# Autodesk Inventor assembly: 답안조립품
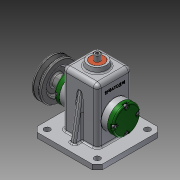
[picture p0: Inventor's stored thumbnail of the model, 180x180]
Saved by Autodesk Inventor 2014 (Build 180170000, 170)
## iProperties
Created: 2016-02
Part Number: 답안조립품
Document SubType Name: Assembly
Designer: Administrator
Author: Administrator
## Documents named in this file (16)
- C:\Users\Administrator\Desktop\460211V1036\답안조립품.iam
- C:\Users\Administrator\Desktop\460211V1036\1-본체.ipt
- C:\Users\Administrator\Desktop\460211V1036\V벨트풀리.ipt
- C:\Users\Administrator\Desktop\460211V1036\고정핀 1.2 x 10.ipt
- C:\Users\Administrator\Desktop\460211V1036\뒤커버.ipt
- C:\Users\Administrator\Desktop\460211V1036\링크.ipt
- C:\Users\Administrator\Desktop\460211V1036\멈춤나사 M3x8.ipt
- C:\Users\Administrator\Desktop\460211V1036\베어링 12 x 32 x 10.ipt
- C:\Users\Administrator\Desktop\460211V1036\볼트 M4 x 12.ipt
- C:\Users\Administrator\Desktop\460211V1036\부시.ipt
- C:\Users\Administrator\Desktop\460211V1036\슬라이드.ipt
- C:\Users\Administrator\Desktop\460211V1036\앞커버.ipt
- C:\Users\Administrator\Desktop\460211V1036\오일실 12 25 7.ipt
- C:\Users\Administrator\Desktop\460211V1036\키 4 x 4 x 10.ipt
- C:\Users\Administrator\Desktop\460211V1036\편심축.ipt
- C:\Users\Administrator\Desktop\460211V1036\핀 5 x 18.ipt
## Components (12 placed, 5 different names)
1. 1-본체:1 — 각도:1, 각도:2, 각도:3, 각도:4
2. V벨트풀리:1
3. 고정핀 1.2 x 10:1 — 각도:4
4. 핀 5 x 18:1
5. ISO 4762 M4 x 12:2 — 각도:2
6. ISO 4762 M4 x 12:1 — 각도:1
7. ISO 4762 M4 x 12:3
8. ISO 4762 M4 x 12:4
9. ISO 4762 M4 x 12:5
10. ISO 4762 M4 x 12:6
11. ISO 4762 M4 x 12:7
12. ISO 4762 M4 x 12:8
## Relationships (4: Angle 4)
- 각도:1 [Angle]: 1-본체:1 ↔ ISO 4762 M4 x 12:1
- 각도:2 [Angle]: 1-본체:1 ↔ ISO 4762 M4 x 12:2
- 각도:3 [Angle]: 1-본체:1
- 각도:4 [Angle]: 1-본체:1 ↔ 고정핀 1.2 x 10:1
